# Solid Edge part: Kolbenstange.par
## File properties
Username: bmolnar
Dokumentum tartalom típus: 0
Author: bmolnar
Last saved by: bmolnar
Revision: 82
Sűrűség: 0,000 kg/m^3
Pontosság: 0,990
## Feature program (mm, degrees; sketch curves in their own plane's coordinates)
base feature "unnamed BaseFeature 1"
thread "unnamed Thread 1"
sketch for "unnamed Protrusion 1" plane through (0, 0, -18.5) normal (0, 0, -1) x-axis (0, -1, 0)
  circle centre (0, 0) radius 12.5
extrude "unnamed Protrusion 1" add finite 14 along +normal
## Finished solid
Body 1: solid body, 17 faces, 23 edges, 8 vertices.
  Faces by surface: plane 8, cylinder 4, torus 3, cone 2
  Edges by curve: circle 13, line 6, ellipse 2, intersection 2
Bounding box of the edges (mm; curved faces can reach further): 25.000 x 25.000 x 88.500, from (-12.5, -12.5, -32.5) to (12.5, 12.5, 56).
Cylindrical faces by radius (mm): R2.9 x1, R4 x1, R5 x1, R12.5 x1
Conical faces (half-angle, radius in mm at the cone's reference point): 20 deg R3.5 x1, 60 deg R3.55 x1
Toroidal faces (ring radius, tube radius in mm): R3.3 r0.4 x2, R3.8 r1.2 x1
Planar faces by outward normal: +x 1, +z 3, -x 1, -z 1, oblique 2
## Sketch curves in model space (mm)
circle centre (0, 0, -18.5) radius 12.5
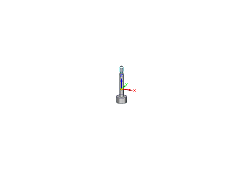
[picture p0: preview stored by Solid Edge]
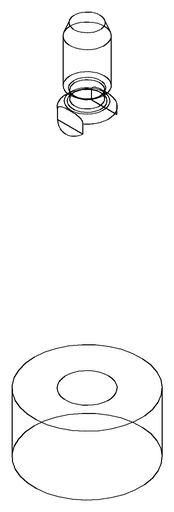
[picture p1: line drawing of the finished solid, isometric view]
